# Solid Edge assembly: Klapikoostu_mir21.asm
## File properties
Author: Türk
Template: Iso Assembly.asm
Last saved by: Türk
Revision: 3
Application: Solid Edge
Username: Türk
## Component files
Klapipuks.par
Klapp.par
Klapi vedru_mir1.par
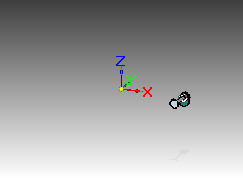
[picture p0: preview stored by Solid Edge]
